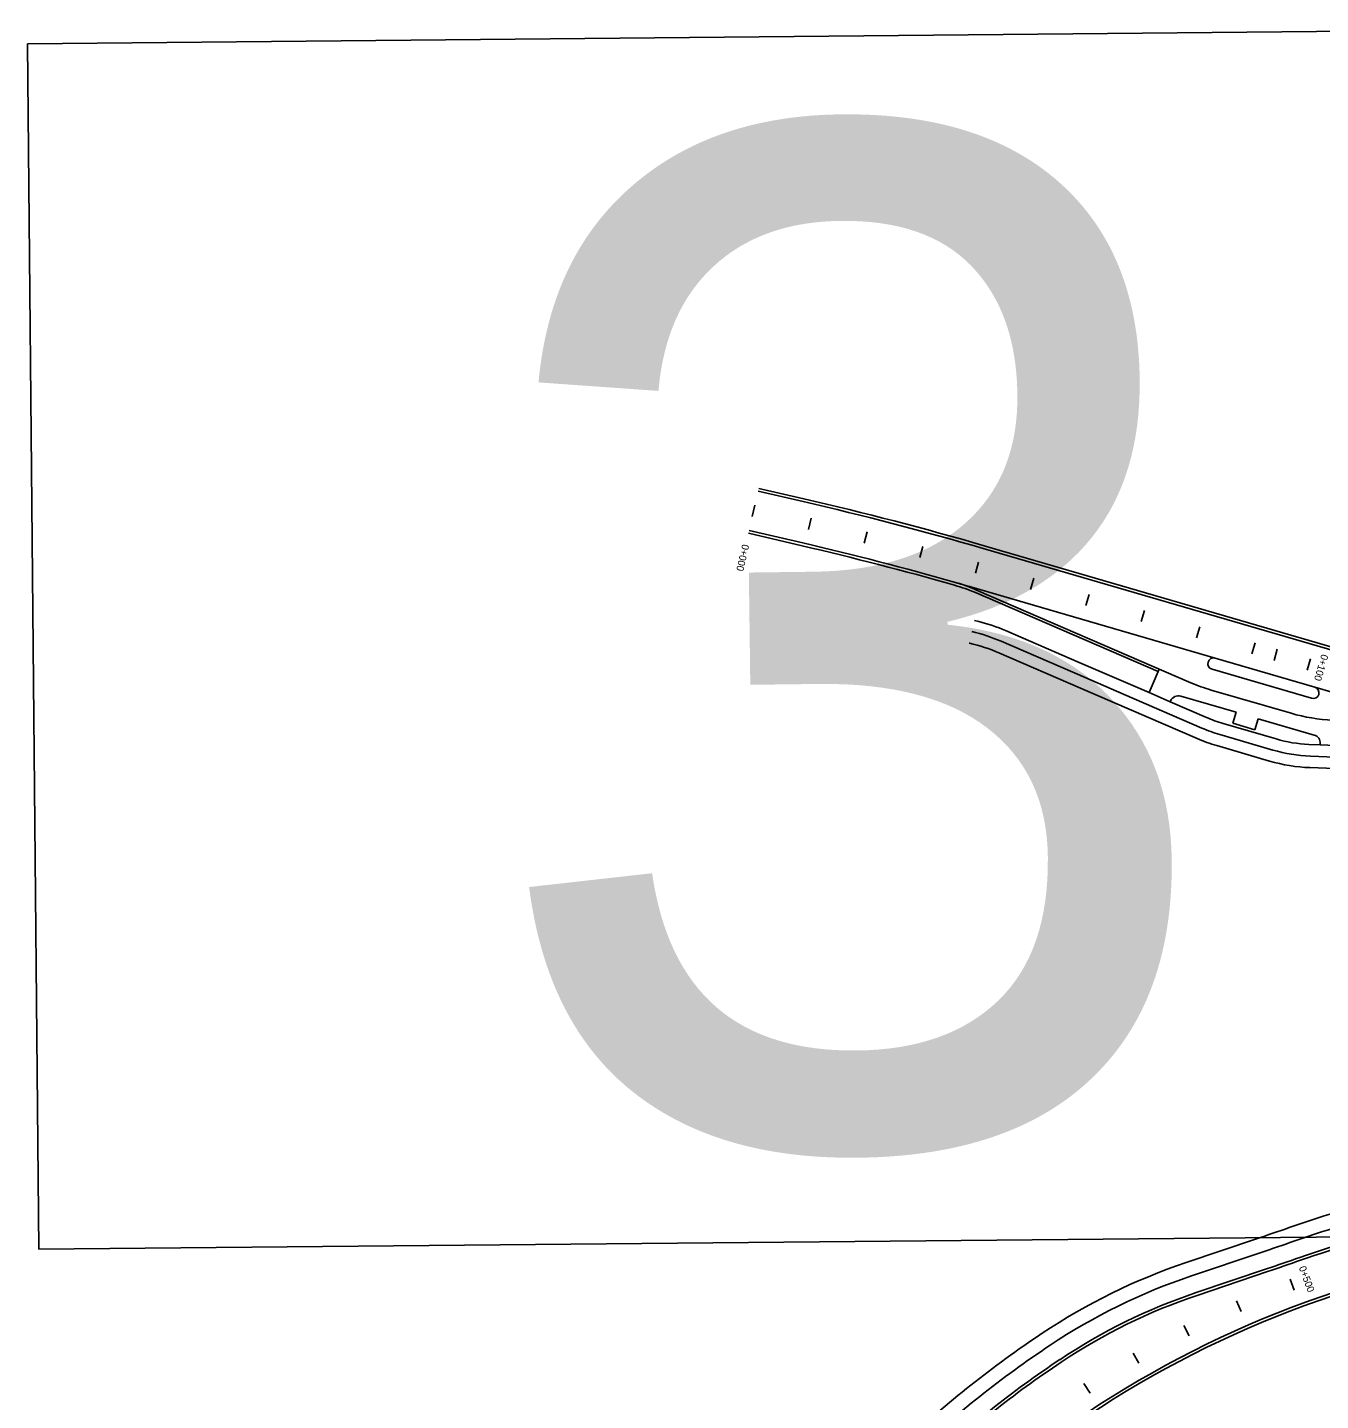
# Model space of a CAD drawing. Extents: x 6503541 to 6503743, y 5888004 to 5888145.
# Drawn here: x 6503553.36 to 6503558.74, y 5888012.75 to 5888018.47 of the extents above; entities that cross this region are included whole.
import ezdxf

# ---------------------------------------------------------------- set-up
doc = ezdxf.new("R2010")
doc.units = 0
doc.layers.add('12', color=7, linetype='Continuous')
doc.layers.add('tabela', color=7, linetype='Continuous')

msp = doc.modelspace()

# ---------------------------------------------------------------- linework, layer by layer
at = {"layer": '12'}
for p, q in [((6503556.5898, 5888016.4945), (6503556.4025, 5888016.5375)), ((6503556.5925, 5888016.5062), (6503556.4052, 5888016.5492)), ((6503556.5858, 5888016.3107), (6503556.3621, 5888016.3627)), ((6503556.5885, 5888016.3224), (6503556.3648, 5888016.3744)), ((6503559.2051, 5888015.7555), (6503557.3402, 5888016.2993)), ((6503559.2085, 5888015.767), (6503557.3436, 5888016.3108)), ((6503557.2932, 5888016.138), (6503558.3064, 5888015.8426)), ((6503558.0683, 5888015.7865), (6503557.3073, 5888016.1155)), ((6503558.2052, 5888015.7403), (6503557.3121, 5888016.1265)), ((6503557.3219, 5888015.9949), (6503557.3036, 5888015.9995)), ((6503557.739, 5888015.825), (6503557.433, 5888015.9573)), ((6503557.283, 5888015.9049), (6503557.2817, 5888015.9052)), ((6503557.7449, 5888015.7178), (6503557.4056, 5888015.8645)), ((6503557.764, 5888015.7619), (6503557.4146, 5888015.9129)), ((6503558.5514, 5888015.8336), (6503558.5648, 5888015.8797)), ((6503558.0305, 5888015.699), (6503557.739, 5888015.825)), ((6503558.3064, 5888015.8426), (6503558.7211, 5888015.7216)), ((6503557.9276, 5888015.6911), (6503557.764, 5888015.7619)), ((6503558.0305, 5888015.699), (6503558.0731, 5888015.7975)), ((6503558.2929, 5888015.7965), (6503558.7077, 5888015.6755)), ((6503558.2311, 5888015.5076), (6503557.7449, 5888015.7178)), ((6503558.0305, 5888015.699), (6503558.1186, 5888015.6609)), ((6503558.2894, 5888015.71), (6503558.6221, 5888015.613)), ((6503558.7211, 5888015.7216), (6503559.1581, 5888015.5942)), ((6503558.2502, 5888015.5517), (6503557.9276, 5888015.6911)), ((6503558.1186, 5888015.6609), (6503558.12, 5888015.6641)), ((6503558.2692, 5888015.5957), (6503558.1186, 5888015.6609)), ((6503558.1631, 5888015.6843), (6503558.3929, 5888015.6173)), ((6503558.3794, 5888015.5713), (6503558.3929, 5888015.6173)), ((6503558.4716, 5888015.5444), (6503558.485, 5888015.5905)), ((6503558.485, 5888015.5905), (6503558.718, 5888015.5225)), ((6503558.3259, 5888015.5244), (6503558.5463, 5888015.4601)), ((6503558.3394, 5888015.5704), (6503558.5597, 5888015.5062)), ((6503558.3794, 5888015.5713), (6503558.4716, 5888015.5444)), ((6503558.3125, 5888015.4783), (6503558.5329, 5888015.414)), ((6503558.6957, 5888015.483), (6503558.7437, 5888015.4811)), ((6503558.7439, 5888015.4866), (6503558.7437, 5888015.4811)), ((6503558.7437, 5888015.4811), (6503558.8396, 5888015.4774)), ((6503558.7026, 5888015.4347), (6503559.2283, 5888015.4143)), ((6503558.7007, 5888015.3867), (6503559.2265, 5888015.3663)), ((6503558.1847, 5888013.3255), (6503558.4781, 5888013.4243)), ((6503558.2038, 5888013.2686), (6503558.4973, 5888013.3675)), ((6503558.2268, 5888013.2004), (6503558.5202, 5888013.2993)), ((6503558.2306, 5888013.189), (6503558.5241, 5888013.2879))]:
    msp.add_line(p, q, dxfattribs=at)
for points in [[(6503556.3891, 5888016.4793), (6503556.3783, 5888016.4325)], [(6503556.6121, 5888016.3785), (6503556.623, 5888016.4253)], [(6503556.8449, 5888016.3221), (6503556.8566, 5888016.3686)], [(6503557.0766, 5888016.2613), (6503557.0892, 5888016.3077)], [(6503557.3072, 5888016.1964), (6503557.3206, 5888016.2425)], [(6503557.5376, 5888016.1292), (6503557.551, 5888016.1753)], [(6503557.768, 5888016.062), (6503557.7814, 5888016.1081)], [(6503557.9984, 5888015.9949), (6503558.0118, 5888016.0409)], [(6503558.2288, 5888015.9277), (6503558.2423, 5888015.9738)], [(6503558.4592, 5888015.8605), (6503558.4727, 5888015.9066)], [(6503558.7031, 5888015.8394), (6503558.6896, 5888015.7933)], [(6503558.7031, 5888015.8394), (6503558.6896, 5888015.7933)], [(6503558.6185, 5888013.2559), (6503558.6351, 5888013.2108)], [(6503558.4136, 5888013.122), (6503558.3945, 5888013.166)], [(6503558.1976, 5888013.0206), (6503558.176, 5888013.0635)], [(6503557.9878, 5888012.9071), (6503557.9638, 5888012.9486)], [(6503557.7848, 5888012.7817), (6503557.7584, 5888012.8218)]]:
    msp.add_lwpolyline(points, dxfattribs=at)
for centre, radius, start, end in [((6503553.6215, 5888003.5464), 13.284, 73.74322, 77.08796), ((6503553.6215, 5888003.5464), 13.296, 73.74322, 77.08796), ((6503553.6215, 5888003.5464), 13.116, 74.05731, 76.92547), ((6503553.6215, 5888003.5464), 13.104, 74.05731, 76.92547), ((6503553.6215, 5888003.5464), 13.116, 73.74322, 74.05883), ((6503557.0263, 5888015.4656), 0.72, 66.6182, 74.0573), ((6503557.0263, 5888015.4656), 0.708, 66.6182, 74.0573), ((6503557.1473, 5888015.2964), 0.72, 66.6182, 75.9685), ((6503557.1289, 5888015.252), 0.72, 66.6182, 76.839), ((6503557.1198, 5888015.2037), 0.72, 66.6182, 76.9022), ((6503558.2997, 5888015.8195), 0.024, 73.7432, 253.3806), ((6503558.491, 5888016.4012), 0.72, 246.6182, 253.7432), ((6503558.7144, 5888015.6986), 0.024, 253.7432, 73.7432), ((6503558.153, 5888015.6498), 0.036, 73.7432, 156.6182), ((6503558.5073, 5888016.1465), 0.6, 246.6192, 253.7432), ((6503558.8237, 5888016.3042), 0.72, 253.7432, 267.7795), ((6503558.5073, 5888016.1465), 0.648, 246.6182, 253.7432), ((6503558.7079, 5888015.488), 0.036, 357.7795, 73.7432), ((6503558.5073, 5888016.1465), 0.696, 246.6182, 253.7432), ((6503558.7277, 5888016.0822), 0.6, 253.7432, 266.9453), ((6503558.7277, 5888016.0822), 0.696, 253.7432, 267.7795), ((6503558.7277, 5888016.0822), 0.648, 253.7432, 267.7795), ((6503560.0791, 5888009.2925), 4.428, 102.9531, 109.3177), ((6503560.0791, 5888009.2925), 4.368, 102.9531, 109.3177), ((6503554.6923, 5888024.6597), 11.856, 288.62142, 289.31766), ((6503560.0791, 5888009.2925), 4.296, 102.7923, 109.3177), ((6503560.0791, 5888009.2925), 4.284, 102.9531, 109.3177), ((6503554.6923, 5888024.6597), 11.916, 288.62142, 289.31766), ((6503558.997, 5888010.9146), 2.544, 108.6214, 123.7072), ((6503554.6923, 5888024.6597), 11.988, 288.62142, 289.31766), ((6503554.6923, 5888024.6597), 12, 288.62142, 289.31766), ((6503560.1475, 5888009.1346), 4.284, 105.7149, 133.0812), ((6503560.1475, 5888009.1346), 4.272, 105.8935, 133.0812), ((6503558.997, 5888010.9146), 2.484, 108.6214, 123.7072), ((6503558.997, 5888010.9146), 2.412, 108.6214, 123.7072), ((6503558.997, 5888010.9146), 2.4, 108.6214, 123.7072), ((6503560.0791, 5888009.2925), 4.494, 123.7072, 133.0812), ((6503560.0791, 5888009.2925), 4.434, 123.7072, 133.0812), ((6503560.0791, 5888009.2925), 4.362, 123.7072, 133.0812), ((6503560.0791, 5888009.2925), 4.35, 123.7072, 133.0812)]:
    msp.add_arc(centre, radius, start, end, dxfattribs=at)
at = {"layer": 'tabela'}
for p, q in [((6503553.3599, 5888018.4018), (6503560.5953, 5888018.4693)), ((6503553.3599, 5888018.4018), (6503560.5953, 5888018.4693)), ((6503553.4067, 5888013.3817), (6503553.3599, 5888018.4018)), ((6503553.4067, 5888013.3817), (6503553.3599, 5888018.4018)), ((6503560.6422, 5888013.4492), (6503553.4067, 5888013.3817)), ((6503560.6422, 5888013.4492), (6503553.4067, 5888013.3817))]:
    msp.add_line(p, q, dxfattribs=at)

# ---------------------------------------------------------------- texts
at = {"layer": '12'}
for s, height, rotation, p in [('3', 4.223, 0.7393, (6503555.2478, 5888013.8018)), ('0+000', 0.03, 257.0031, (6503556.3367, 5888016.319)), ('0+100', 0.03, 253.7433, (6503558.749, 5888015.8612)), ('0+500', 0.03, 290.2309, (6503558.6538, 5888013.3046))]:
    msp.add_text(s, height=height, rotation=rotation, dxfattribs=at).set_placement(p)

doc.saveas('drawing.dxf')
